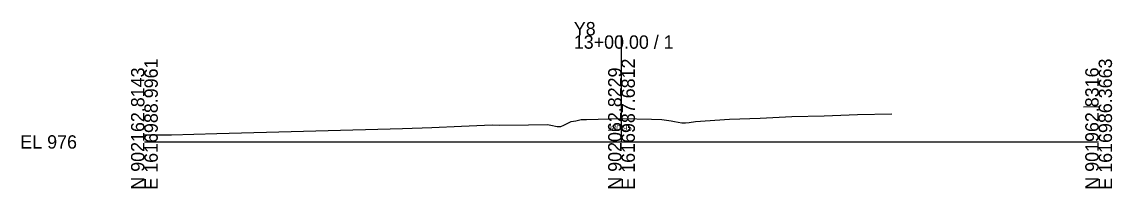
# Model space of a CAD drawing. Extents: x -26 to 1403, y -10 to 3025.
# Drawn here: x -25.7 to 202.8, y 2990.3 to 3025.2 of the extents above; entities that cross this region are included whole.
import ezdxf

# ---------------------------------------------------------------- set-up
doc = ezdxf.new("R2010")
doc.units = 0
for name, color, linetype in [('Exist Cross Section Cell', 7, 'Continuous'), ('Exist XS Center Line Elevation Label', 7, 'Continuous'), ('Exist XS Ground Line', 7, 'Continuous')]:
    doc.layers.add(name, color=color, linetype=linetype)

msp = doc.modelspace()

# ---------------------------------------------------------------- linework, layer by layer
at = {"layer": 'Exist Cross Section Cell'}
for p, q in [((100, 3000), (100, 3022.34)), ((0, 3000), (100, 3000)), ((100, 3000), (200, 3000))]:
    msp.add_line(p, q, dxfattribs=at)
at = {"layer": 'Exist XS Ground Line'}
for p, q in [((129.06, 3005.02), (135.69, 3005.31)), ((135.69, 3005.31), (142.49, 3005.45)), ((142.49, 3005.45), (149.47, 3005.72)), ((149.47, 3005.72), (156.63, 3005.91)), ((196.84, 3007.35), (200, 3007.45)), ((54.08, 3002.79), (60.23, 3003.05)), ((60.23, 3003.05), (66.49, 3003.32)), ((66.49, 3003.32), (72.87, 3003.57)), ((72.87, 3003.57), (74.47, 3003.53)), ((74.47, 3003.53), (80.5, 3003.6)), ((80.5, 3003.6), (84.49, 3003.65)), ((84.49, 3003.65), (85.18, 3003.51)), ((85.18, 3003.51), (86.54, 3003.27)), ((86.54, 3003.27), (87.29, 3003.27)), ((87.29, 3003.27), (87.88, 3003.52)), ((87.88, 3003.52), (89.46, 3004.28)), ((89.46, 3004.28), (90.42, 3004.46)), ((90.42, 3004.46), (91, 3004.57)), ((91, 3004.57), (91.53, 3004.69)), ((91.53, 3004.69), (92.66, 3004.72)), ((92.66, 3004.72), (100.09, 3004.95)), ((100.09, 3004.95), (106.29, 3004.77)), ((106.29, 3004.77), (108.44, 3004.7)), ((108.44, 3004.7), (109.9, 3004.49)), ((109.9, 3004.49), (110.44, 3004.41)), ((110.44, 3004.41), (111.07, 3004.28)), ((111.07, 3004.28), (112.64, 3003.99)), ((112.64, 3003.99), (113.39, 3003.99)), ((113.39, 3003.99), (114.16, 3004.11)), ((114.16, 3004.11), (115.52, 3004.32)), ((115.52, 3004.32), (122.6, 3004.77)), ((122.6, 3004.77), (129.06, 3005.02)), ((0, 3001.5), (1.09, 3001.5)), ((1.09, 3001.5), (5.65, 3001.49)), ((5.65, 3001.49), (10.34, 3001.62)), ((10.34, 3001.62), (15.17, 3001.75)), ((15.17, 3001.75), (54.08, 3002.79))]:
    msp.add_line(p, q, dxfattribs=at)

# ---------------------------------------------------------------- texts
at = {"layer": 'Exist Cross Section Cell'}
for s, p in [('Y8', (90, 3022.34)), ('13+00.00 / 1', (90, 3019.54)), ('EL 976', (-26, 2998.6))]:
    msp.add_text(s, height=2.8, dxfattribs=at).set_placement(p)
for s, p in [('E 1616988.9961', (2.8, 2990)), ('E 1616987.6812', (102.8, 2990)), ('E 1616986.3663', (202.8, 2990)), ('N 902162.8143', (0, 2990)), ('N 902062.8229', (100, 2990)), ('N 901962.8316', (200, 2990))]:
    msp.add_text(s, height=2.8, rotation=90, dxfattribs=at).set_placement(p)
at = {"layer": 'Exist XS Center Line Elevation Label'}
msp.add_text('980.95', height=1.25, dxfattribs=at).set_placement((97.05, 3002.32))

doc.saveas('drawing.dxf')
